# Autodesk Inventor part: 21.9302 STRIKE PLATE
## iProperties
Created: 2011-01
Part Number: 21.9302 STRIKE PLATE
Material: Steel
Document SubType Name: Sheet Metal
Designer: Administrator
Density: 7.85 g/cm^3
Mass: 23.1954 g
Surface Area: 42.6597 cm^2
Volume: 2.95482 cm^3
Author: Administrator
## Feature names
1. Hole1
2. Plate1
